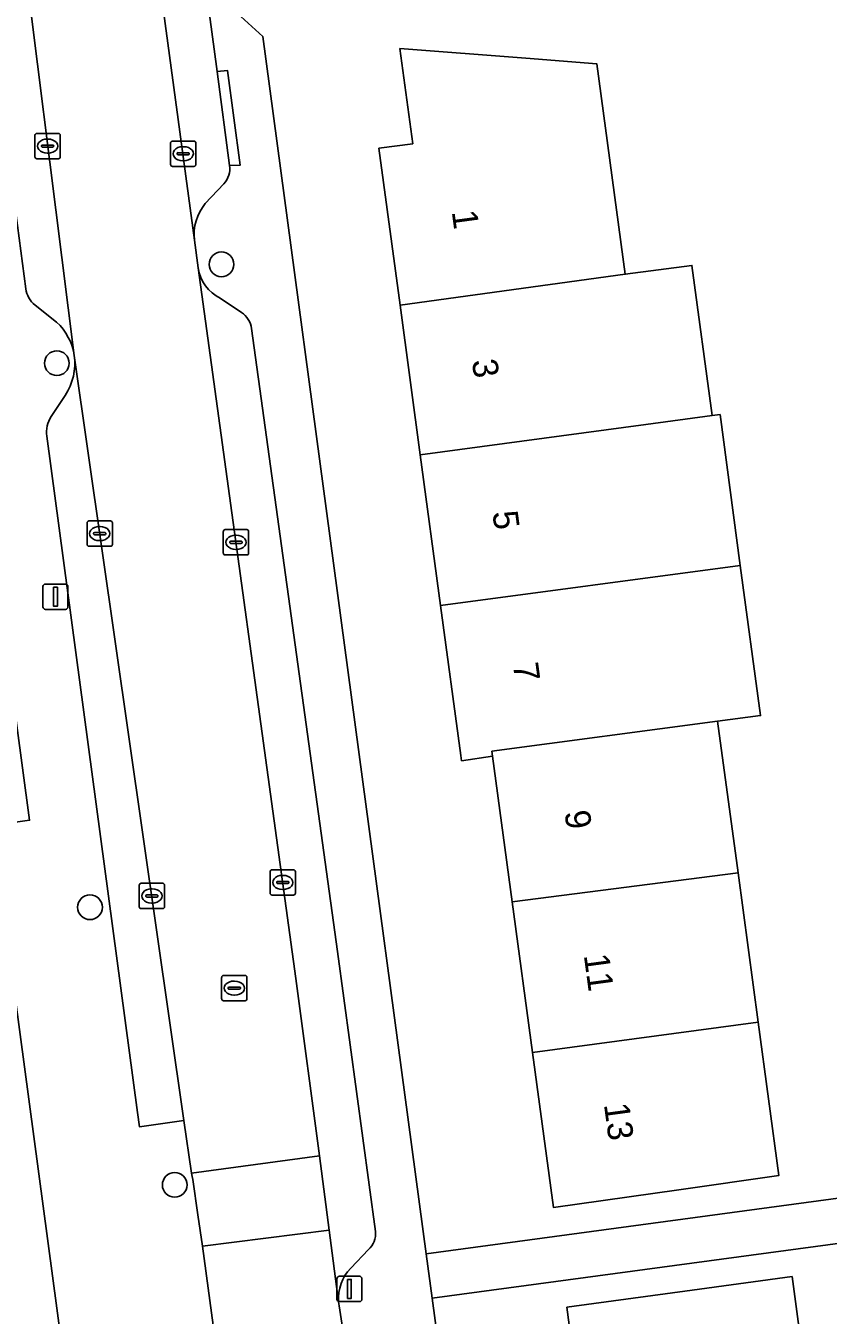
# Model space of a CAD drawing. Extents: x 163426 to 164192, y 380329 to 381641.
# Drawn here: x 163541.2 to 163572.9, y 381442.8 to 381493.9 of the extents above; entities that cross this region are included whole.
import ezdxf

# ---------------------------------------------------------------- set-up
doc = ezdxf.new("R2010")
doc.units = 0
for name, color, linetype in [('IMGEO_Boom', 7, 'Continuous'), ('IMGEO_Erf', 7, 'Continuous'), ('IMGEO_Kolk', 7, 'Continuous'), ('IMGEO_Lichtmast', 7, 'Continuous'), ('IMGEO_Pand', 7, 'Continuous'), ('IMGEO_Pand_nummerreeks', 7, 'Continuous'), ('IMGEO_Parkeervlak_open', 7, 'Continuous'), ('IMGEO_Rijbaan_lokaal_open', 7, 'Continuous'), ('IMGEO_Rioolput', 7, 'Continuous'), ('IMGEO_Voetpad_open', 7, 'Continuous')]:
    doc.layers.add(name, color=color, linetype=linetype)

msp = doc.modelspace()

# ---------------------------------------------------------------- linework, layer by layer
at = {"layer": 'IMGEO_Boom'}
for centre in [(163548.902, 381484.415), (163542.391, 381480.505), (163543.702, 381458.979), (163547.053, 381447.995)]:
    msp.add_circle(centre, 0.489, dxfattribs=at)
at = {"layer": 'IMGEO_Erf'}
for points in [[(163539.823, 381462.212), (163541.312, 381462.422), (163536.277, 381500), (163535.961, 381502.355), (163535.005, 381502.264), (163513.264, 381499.338), (163523.981, 381419.703), (163545.149, 381422.545)], [(163570.944, 381448.362), (163566.984, 381447.803), (163562.033, 381447.104), (163561.206, 381453.238), (163560.404, 381459.187), (163559.625, 381464.96), (163558.397, 381464.774), (163558.368, 381464.987), (163557.569, 381470.913), (163556.764, 381476.879), (163555.964, 381482.806), (163555.127, 381489.007), (163556.465, 381489.187), (163555.958, 381492.955), (163560.943, 381492.567), (163563.751, 381492.348), (163564.872, 381484.021), (163567.508, 381484.373), (163568.308, 381478.43), (163568.618, 381478.472), (163569.422, 381472.502), (163570.222, 381466.564), (163568.524, 381466.338), (163569.331, 381460.342), (163570.128, 381454.426)]]:
    msp.add_lwpolyline(points, close=True, dxfattribs=at)
for points in [[(163549.67, 381494.227), (163550.532, 381493.434), (163556.995, 381445.271), (163583.148, 381448.798)], [(163581.439, 381442.03), (163580.811, 381446.687), (163557.232, 381443.507), (163566.206, 381376.628)], [(163563.384, 381436.962), (163562.564, 381443.153), (163567.519, 381443.827), (163571.471, 381444.365), (163572.3, 381438.127)]]:
    msp.add_lwpolyline(points, dxfattribs=at)
at = {"layer": 'IMGEO_Kolk'}
for p, q in [((163541.525, 381488.668), (163541.525, 381489.52)), ((163541.6, 381489.594), (163542.452, 381489.594)), ((163542.013, 381489.374), (163542.038, 381489.374)), ((163542.526, 381489.52), (163542.526, 381488.668)), ((163546.962, 381489.291), (163547.814, 381489.291)), ((163541.784, 381489.088), (163541.784, 381489.1)), ((163542.222, 381489.051), (163541.824, 381489.051)), ((163541.827, 381489.137), (163542.225, 381489.137)), ((163542.036, 381488.814), (163542.011, 381488.814)), ((163542.268, 381489.1), (163542.268, 381489.088)), ((163546.887, 381488.365), (163546.887, 381489.217)), ((163547.146, 381488.785), (163547.146, 381488.797)), ((163547.584, 381488.748), (163547.186, 381488.748)), ((163547.189, 381488.834), (163547.587, 381488.834)), ((163547.375, 381489.071), (163547.4, 381489.071)), ((163547.63, 381488.797), (163547.63, 381488.785)), ((163547.888, 381489.217), (163547.888, 381488.365)), ((163542.452, 381488.594), (163541.6, 381488.594)), ((163547.814, 381488.291), (163546.962, 381488.291)), ((163547.398, 381488.511), (163547.373, 381488.511)), ((163543.587, 381473.337), (163543.587, 381474.189)), ((163543.662, 381474.263), (163544.514, 381474.263)), ((163544.075, 381474.043), (163544.1, 381474.043)), ((163544.588, 381474.189), (163544.588, 381473.337)), ((163543.846, 381473.757), (163543.846, 381473.769)), ((163544.284, 381473.72), (163543.886, 381473.72)), ((163543.889, 381473.806), (163544.287, 381473.806)), ((163544.098, 381473.483), (163544.073, 381473.483)), ((163544.33, 381473.769), (163544.33, 381473.757)), ((163548.975, 381472.992), (163548.975, 381473.844)), ((163549.05, 381473.918), (163549.902, 381473.918)), ((163549.277, 381473.461), (163549.675, 381473.461)), ((163549.463, 381473.698), (163549.488, 381473.698)), ((163549.976, 381473.844), (163549.976, 381472.992)), ((163544.514, 381473.263), (163543.662, 381473.263)), ((163549.234, 381473.412), (163549.234, 381473.424)), ((163549.672, 381473.375), (163549.274, 381473.375)), ((163549.486, 381473.138), (163549.461, 381473.138)), ((163549.718, 381473.424), (163549.718, 381473.412)), ((163549.902, 381472.918), (163549.05, 381472.918)), ((163550.827, 381459.533), (163550.827, 381460.385)), ((163550.902, 381460.459), (163551.754, 381460.459)), ((163551.315, 381460.239), (163551.34, 381460.239)), ((163551.828, 381460.385), (163551.828, 381459.533)), ((163545.648, 381459), (163545.648, 381459.852)), ((163545.723, 381459.926), (163546.575, 381459.926)), ((163546.136, 381459.706), (163546.161, 381459.706)), ((163546.649, 381459.852), (163546.649, 381459)), ((163551.086, 381459.953), (163551.086, 381459.965)), ((163551.524, 381459.916), (163551.126, 381459.916)), ((163551.129, 381460.002), (163551.527, 381460.002)), ((163551.338, 381459.679), (163551.313, 381459.679)), ((163551.57, 381459.965), (163551.57, 381459.953)), ((163545.907, 381459.42), (163545.907, 381459.432)), ((163546.345, 381459.383), (163545.947, 381459.383)), ((163545.95, 381459.469), (163546.348, 381459.469)), ((163546.391, 381459.432), (163546.391, 381459.42)), ((163551.754, 381459.459), (163550.902, 381459.459)), ((163546.575, 381458.926), (163545.723, 381458.926)), ((163546.159, 381459.146), (163546.134, 381459.146))]:
    msp.add_line(p, q, dxfattribs=at)
for points in [[(163541.525, 381488.668), (163541.525, 381489.52)], [(163541.6, 381489.594), (163542.452, 381489.594)], [(163542.526, 381489.52), (163542.526, 381488.668)], [(163546.962, 381489.291), (163547.814, 381489.291)], [(163546.887, 381488.365), (163546.887, 381489.217)], [(163547.888, 381489.217), (163547.888, 381488.365)], [(163542.452, 381488.594), (163541.6, 381488.594)], [(163547.814, 381488.291), (163546.962, 381488.291)], [(163543.587, 381473.337), (163543.587, 381474.189)], [(163543.662, 381474.263), (163544.514, 381474.263)], [(163544.588, 381474.189), (163544.588, 381473.337)], [(163548.975, 381472.992), (163548.975, 381473.844)], [(163549.05, 381473.918), (163549.902, 381473.918)], [(163549.976, 381473.844), (163549.976, 381472.992)], [(163544.514, 381473.263), (163543.662, 381473.263)], [(163549.902, 381472.918), (163549.05, 381472.918)], [(163550.827, 381459.533), (163550.827, 381460.385)], [(163550.902, 381460.459), (163551.754, 381460.459)], [(163551.828, 381460.385), (163551.828, 381459.533)], [(163545.648, 381459), (163545.648, 381459.852)], [(163545.723, 381459.926), (163546.575, 381459.926)], [(163546.649, 381459.852), (163546.649, 381459)], [(163551.754, 381459.459), (163550.902, 381459.459)], [(163546.575, 381458.926), (163545.723, 381458.926)]]:
    msp.add_lwpolyline(points, dxfattribs=at)
for centre, radius, start, end in [((163541.602, 381489.518), 0.0765, 91.552, 178.448), ((163541.602, 381489.518), 0.0765, 91.552, 178.448), ((163542.45, 381489.518), 0.0765, 1.552, 88.448), ((163542.45, 381489.518), 0.0765, 1.552, 88.448), ((163546.964, 381489.215), 0.0765, 91.552, 178.448), ((163546.964, 381489.215), 0.0765, 91.552, 178.448), ((163547.812, 381489.215), 0.0765, 1.552, 88.448), ((163547.812, 381489.215), 0.0765, 1.552, 88.448), ((163541.824, 381489.097), 0.0403, 85.8775, 175.7526), ((163541.821, 381489.087), 0.0366, 178.938, 274.7102), ((163542.225, 381489.094), 0.043, 264.8664, 352.4533), ((163542.229, 381489.099), 0.0386, 1.7309, 96.639), ((163547.186, 381488.794), 0.0403, 85.8775, 175.7526), ((163547.183, 381488.784), 0.0366, 178.938, 274.7102), ((163547.587, 381488.791), 0.043, 264.8664, 352.4533), ((163547.591, 381488.796), 0.0386, 1.7309, 96.639), ((163541.602, 381488.67), 0.0765, 181.552, 268.448), ((163541.602, 381488.67), 0.0765, 181.552, 268.448), ((163542.45, 381488.67), 0.0765, 271.552, 358.448), ((163542.45, 381488.67), 0.0765, 271.552, 358.448), ((163546.964, 381488.367), 0.0765, 181.552, 268.448), ((163546.964, 381488.367), 0.0765, 181.552, 268.448), ((163547.812, 381488.367), 0.0765, 271.552, 358.448), ((163547.812, 381488.367), 0.0765, 271.552, 358.448), ((163543.664, 381474.187), 0.0765, 91.552, 178.448), ((163543.664, 381474.187), 0.0765, 91.552, 178.448), ((163544.512, 381474.187), 0.0765, 1.552, 88.448), ((163544.512, 381474.187), 0.0765, 1.552, 88.448), ((163543.886, 381473.766), 0.0403, 85.8775, 175.7526), ((163543.883, 381473.756), 0.0366, 178.938, 274.7102), ((163544.287, 381473.763), 0.043, 264.8664, 352.4533), ((163544.291, 381473.768), 0.0386, 1.7309, 96.639), ((163549.052, 381473.842), 0.0765, 91.552, 178.448), ((163549.052, 381473.842), 0.0765, 91.552, 178.448), ((163549.274, 381473.421), 0.0403, 85.8775, 175.7526), ((163549.679, 381473.423), 0.0386, 1.7309, 96.639), ((163549.9, 381473.842), 0.0765, 1.552, 88.448), ((163549.9, 381473.842), 0.0765, 1.552, 88.448), ((163543.664, 381473.339), 0.0765, 181.552, 268.448), ((163543.664, 381473.339), 0.0765, 181.552, 268.448), ((163544.512, 381473.339), 0.0765, 271.552, 358.448), ((163544.512, 381473.339), 0.0765, 271.552, 358.448), ((163549.052, 381472.994), 0.0765, 181.552, 268.448), ((163549.052, 381472.994), 0.0765, 181.552, 268.448), ((163549.271, 381473.411), 0.0366, 178.938, 274.7102), ((163549.675, 381473.418), 0.043, 264.8664, 352.4533), ((163549.9, 381472.994), 0.0765, 271.552, 358.448), ((163549.9, 381472.994), 0.0765, 271.552, 358.448), ((163550.904, 381460.383), 0.0765, 91.552, 178.448), ((163550.904, 381460.383), 0.0765, 91.552, 178.448), ((163551.752, 381460.383), 0.0765, 1.552, 88.448), ((163551.752, 381460.383), 0.0765, 1.552, 88.448), ((163545.725, 381459.85), 0.0765, 91.552, 178.448), ((163545.725, 381459.85), 0.0765, 91.552, 178.448), ((163546.573, 381459.85), 0.0765, 1.552, 88.448), ((163546.573, 381459.85), 0.0765, 1.552, 88.448), ((163551.126, 381459.962), 0.0403, 85.8775, 175.7526), ((163551.123, 381459.952), 0.0366, 178.938, 274.7102), ((163551.527, 381459.959), 0.043, 264.8664, 352.4533), ((163551.531, 381459.964), 0.0386, 1.7309, 96.639), ((163545.947, 381459.429), 0.0403, 85.8775, 175.7526), ((163545.944, 381459.419), 0.0366, 178.938, 274.7102), ((163546.348, 381459.426), 0.043, 264.8664, 352.4533), ((163546.352, 381459.431), 0.0386, 1.7309, 96.639), ((163550.904, 381459.535), 0.0765, 181.552, 268.448), ((163550.904, 381459.535), 0.0765, 181.552, 268.448), ((163551.752, 381459.535), 0.0765, 271.552, 358.448), ((163551.752, 381459.535), 0.0765, 271.552, 358.448), ((163545.725, 381459.002), 0.0765, 181.552, 268.448), ((163545.725, 381459.002), 0.0765, 181.552, 268.448), ((163546.573, 381459.002), 0.0765, 271.552, 358.448), ((163546.573, 381459.002), 0.0765, 271.552, 358.448)]:
    msp.add_arc(centre, radius, start, end, dxfattribs=at)
for centre, major_axis, ratio, start_param, end_param in [((163542.012, 381489.094), (-0.387, 0.002), 0.722429, 4.712389, 7.853982), ((163542.037, 381489.094), (-0.39, 0.002), 0.717154, 1.570796, 4.712389), ((163547.374, 381488.791), (-0.387, 0.002), 0.722429, 4.712389, 7.853982), ((163547.399, 381488.791), (-0.39, 0.002), 0.717154, 1.570796, 4.712389), ((163544.074, 381473.763), (-0.387, 0.002), 0.722429, 4.712389, 7.853982), ((163544.099, 381473.763), (-0.39, 0.002), 0.717154, 1.570796, 4.712389), ((163549.462, 381473.418), (-0.387, 0.002), 0.722429, 4.712389, 7.853982), ((163549.487, 381473.418), (-0.39, 0.002), 0.717154, 1.570796, 4.712389), ((163551.314, 381459.959), (-0.387, 0.002), 0.722429, 4.712389, 7.853982), ((163551.339, 381459.959), (-0.39, 0.002), 0.717154, 1.570796, 4.712389), ((163546.135, 381459.426), (-0.387, 0.002), 0.722429, 4.712389, 7.853982), ((163546.16, 381459.426), (-0.39, 0.002), 0.717154, 1.570796, 4.712389)]:
    msp.add_ellipse(centre, major_axis=major_axis, ratio=ratio, start_param=start_param, end_param=end_param, dxfattribs=at)
at = {"layer": 'IMGEO_Lichtmast'}
for p, q in [((163541.842, 381470.864), (163541.842, 381471.664)), ((163541.842, 381471.664), (163541.842, 381470.864)), ((163541.942, 381471.764), (163542.732, 381471.764)), ((163542.732, 381471.764), (163541.942, 381471.764)), ((163542.832, 381471.664), (163542.832, 381470.864)), ((163542.832, 381470.864), (163542.832, 381471.664)), ((163542.732, 381470.764), (163541.942, 381470.764)), ((163541.942, 381470.764), (163542.732, 381470.764)), ((163553.567, 381444.377), (163554.357, 381444.377)), ((163554.357, 381444.377), (163553.567, 381444.377)), ((163553.467, 381443.477), (163553.467, 381444.277)), ((163553.467, 381444.277), (163553.467, 381443.477)), ((163554.457, 381444.277), (163554.457, 381443.477)), ((163554.457, 381443.477), (163554.457, 381444.277)), ((163554.357, 381443.377), (163553.567, 381443.377)), ((163553.567, 381443.377), (163554.357, 381443.377))]:
    msp.add_line(p, q, dxfattribs=at)
for points in [[(163542.262, 381471.639), (163542.412, 381471.639), (163542.412, 381470.889), (163542.262, 381470.889), (163542.262, 381471.639)], [(163553.887, 381444.252), (163554.037, 381444.252), (163554.037, 381443.502), (163553.887, 381443.502), (163553.887, 381444.252)]]:
    msp.add_lwpolyline(points, dxfattribs=at)
for centre, start, end in [((163541.942, 381471.664), 90, 180), ((163541.942, 381471.664), 90, 180), ((163542.732, 381471.664), 0, 90), ((163542.732, 381471.664), 360, 90), ((163541.942, 381470.864), 180, 270), ((163541.942, 381470.864), 180, 270), ((163542.732, 381470.864), 270, 0), ((163542.732, 381470.864), 270, 0), ((163553.567, 381444.277), 90, 180), ((163553.567, 381444.277), 90, 180), ((163554.357, 381444.277), 0, 90), ((163554.357, 381444.277), 360, 90), ((163553.567, 381443.477), 180, 270), ((163553.567, 381443.477), 180, 270), ((163554.357, 381443.477), 270, 0), ((163554.357, 381443.477), 270, 0)]:
    msp.add_arc(centre, 0.1, start, end, dxfattribs=at)
at = {"layer": 'IMGEO_Pand'}
for points in [[(163555.964, 381482.806), (163564.872, 381484.021), (163563.751, 381492.348), (163560.943, 381492.567), (163555.958, 381492.955), (163556.465, 381489.187), (163555.127, 381489.007)], [(163556.764, 381476.879), (163565.691, 381478.079), (163568.308, 381478.43), (163567.508, 381484.373), (163564.872, 381484.021), (163555.964, 381482.806)], [(163569.422, 381472.502), (163568.618, 381478.472), (163568.308, 381478.43), (163565.691, 381478.079), (163556.764, 381476.879), (163557.569, 381470.913)], [(163569.422, 381472.502), (163557.569, 381470.913), (163558.368, 381464.987), (163558.397, 381464.774), (163559.625, 381464.96), (163559.599, 381465.151), (163568.524, 381466.338), (163570.222, 381466.564)], [(163568.524, 381466.338), (163559.599, 381465.151), (163559.625, 381464.96), (163560.404, 381459.187), (163569.331, 381460.342)], [(163570.128, 381454.426), (163569.331, 381460.342), (163560.404, 381459.187), (163561.206, 381453.238)], [(163570.128, 381454.426), (163561.206, 381453.238), (163562.033, 381447.104), (163566.984, 381447.803), (163570.944, 381448.362)], [(163563.384, 381436.962), (163572.3, 381438.127), (163571.471, 381444.365), (163567.519, 381443.827), (163562.564, 381443.153)]]:
    msp.add_lwpolyline(points, close=True, dxfattribs=at)
at = {"layer": 'IMGEO_Parkeervlak_open'}
for points in [[(163542.971, 381521.306), (163545.852, 381500), (163547.83, 381485.368)], [(163549.225, 381488.332), (163548.727, 381492.039), (163547.658, 381500), (163545.129, 381518.832)], [(163537.364, 381512.278), (163538.982, 381500), (163541.163, 381483.452)], [(163543.08, 381480.808), (163540.658, 381500)], [(163548.263, 381486.824), (163548.992, 381487.606)], [(163547.979, 381484.273), (163551.848, 381456.16), (163552.773, 381449.148), (163553.162, 381446.201), (163553.536, 381443.371)], [(163541.53, 381482.804), (163542.383, 381482.127)], [(163549.695, 381482.511), (163548.854, 381483.073)], [(163554.995, 381446.148), (163553.497, 381457.225), (163550.094, 381481.871)], [(163541.994, 381477.616), (163545.579, 381450.857), (163545.661, 381450.286), (163547.416, 381450.538), (163543.08, 381480.808)], [(163542.723, 381479.23), (163542.17, 381478.391)], [(163554.012, 381444.698), (163554.715, 381445.435)]]:
    msp.add_lwpolyline(points, dxfattribs=at)
for centre, radius, start, end in [((163548.321, 381488.222), 0.911, 317.4577, 6.9557), ((163549.769, 381485.584), 1.951, 140.5252, 186.3509), ((163549.592, 381484.53), 1.633, 189.0479, 243.1487), ((163542.151, 381483.584), 0.997, 187.6006, 231.4502), ((163540.855, 381480.476), 2.25, 8.4886, 47.218), ((163549.183, 381481.747), 0.92, 7.7306, 56.1513), ((163540.788, 381480.497), 2.313, 326.784, 7.7205), ((163543.121, 381477.768), 1.137, 146.7503, 187.6603), ((163554.122, 381446.079), 0.876, 312.6217, 4.4977), ((163555.231, 381443.512), 1.701, 135.7848, 184.749)]:
    msp.add_arc(centre, radius, start, end, dxfattribs=at)
at = {"layer": 'IMGEO_Rijbaan_lokaal_open'}
for points in [[(163547.714, 381448.459), (163552.773, 381449.148), (163551.848, 381456.16), (163547.979, 381484.273), (163547.83, 381485.368), (163545.852, 381500), (163542.971, 381521.306), (163542.879, 381522.123), (163542.729, 381523.405), (163542.764, 381523.704), (163537.726, 381523.034), (163537.691, 381522.857), (163537.994, 381521.009), (163538.748, 381515.131), (163540.658, 381500), (163543.08, 381480.808), (163547.416, 381450.538)], [(163552.773, 381449.148), (163547.714, 381448.459), (163547.744, 381448.327), (163547.772, 381448.204), (163547.973, 381446.804), (163548.151, 381445.563), (163553.162, 381446.201)], [(163553.981, 381440.08), (163553.761, 381441.842), (163553.557, 381443.21), (163553.536, 381443.371), (163553.162, 381446.201), (163548.151, 381445.563), (163548.736, 381441.267), (163548.986, 381439.398), (163554.854, 381395.594), (163559.875, 381396.219)]]:
    msp.add_lwpolyline(points, close=True, dxfattribs=at)
at = {"layer": 'IMGEO_Rioolput'}
for p, q in [((163548.909, 381455.352), (163548.909, 381456.204)), ((163548.984, 381456.278), (163549.836, 381456.278)), ((163549.91, 381456.204), (163549.91, 381455.352)), ((163549.168, 381455.772), (163549.168, 381455.784)), ((163549.606, 381455.735), (163549.208, 381455.735)), ((163549.211, 381455.821), (163549.609, 381455.821)), ((163549.397, 381456.058), (163549.422, 381456.058)), ((163549.652, 381455.784), (163549.652, 381455.772)), ((163549.836, 381455.278), (163548.984, 381455.278)), ((163549.42, 381455.498), (163549.395, 381455.498))]:
    msp.add_line(p, q, dxfattribs=at)
for points in [[(163548.909, 381455.352), (163548.909, 381456.204)], [(163548.984, 381456.278), (163549.836, 381456.278)], [(163549.91, 381456.204), (163549.91, 381455.352)], [(163549.836, 381455.278), (163548.984, 381455.278)]]:
    msp.add_lwpolyline(points, dxfattribs=at)
for centre, radius, start, end in [((163548.986, 381456.202), 0.0765, 91.552, 178.448), ((163548.986, 381456.202), 0.0765, 91.552, 178.448), ((163549.834, 381456.202), 0.0765, 1.552, 88.448), ((163549.834, 381456.202), 0.0765, 1.552, 88.448), ((163549.208, 381455.781), 0.0403, 85.8775, 175.7526), ((163549.205, 381455.771), 0.0366, 178.938, 274.7102), ((163549.609, 381455.778), 0.043, 264.8664, 352.4533), ((163549.613, 381455.783), 0.0386, 1.7309, 96.639), ((163548.986, 381455.354), 0.0765, 181.552, 268.448), ((163548.986, 381455.354), 0.0765, 181.552, 268.448), ((163549.834, 381455.354), 0.0765, 271.552, 358.448), ((163549.834, 381455.354), 0.0765, 271.552, 358.448)]:
    msp.add_arc(centre, radius, start, end, dxfattribs=at)
for centre, major_axis, ratio, start_param, end_param in [((163549.396, 381455.778), (-0.387, 0.002), 0.722429, 4.712389, 7.853982), ((163549.421, 381455.778), (-0.39, 0.002), 0.717154, 1.570796, 4.712389)]:
    msp.add_ellipse(centre, major_axis=major_axis, ratio=ratio, start_param=start_param, end_param=end_param, dxfattribs=at)
at = {"layer": 'IMGEO_Voetpad_open'}
for points in [[(163538.748, 381515.131), (163537.994, 381521.009), (163537.691, 381522.857), (163537.726, 381523.034), (163537.586, 381523.962), (163537.28, 381526.001), (163532.089, 381524.073), (163534.881, 381503.195), (163535.005, 381502.264), (163535.961, 381502.355), (163536.277, 381500), (163541.312, 381462.422), (163539.823, 381462.212), (163545.149, 381422.545), (163545.331, 381421.187), (163551.459, 381375.552), (163552.956, 381375.749), (163557.372, 381342.692), (163557.774, 381339.564)], [(163571.177, 381345.417), (163569.239, 381353.811), (163569.01, 381355.444), (163568.044, 381362.93), (163566.405, 381375.146), (163566.206, 381376.628), (163557.232, 381443.507), (163556.995, 381445.271), (163550.532, 381493.434), (163549.67, 381494.227), (163548.887, 381500), (163545.916, 381521.903)], [(163545.129, 381518.832), (163547.658, 381500), (163548.727, 381492.039), (163549.144, 381492.08), (163549.638, 381488.335), (163549.225, 381488.332)], [(163541.163, 381483.452), (163538.982, 381500), (163537.364, 381512.278)], [(163548.992, 381487.606), (163548.263, 381486.824)], [(163547.83, 381485.368), (163547.979, 381484.273)], [(163542.383, 381482.127), (163541.53, 381482.804)], [(163548.854, 381483.073), (163549.695, 381482.511)], [(163550.094, 381481.871), (163553.497, 381457.225), (163554.995, 381446.148)], [(163542.17, 381478.391), (163542.723, 381479.23)], [(163548.986, 381439.398), (163548.736, 381441.267), (163548.151, 381445.563), (163547.973, 381446.804), (163547.772, 381448.204), (163547.744, 381448.327), (163547.714, 381448.459), (163547.416, 381450.538), (163545.661, 381450.286), (163545.579, 381450.857), (163541.994, 381477.616)], [(163583.148, 381448.798), (163556.995, 381445.271), (163557.232, 381443.507), (163580.811, 381446.687)], [(163554.715, 381445.435), (163554.012, 381444.698)], [(163553.536, 381443.371), (163553.557, 381443.21), (163553.761, 381441.842), (163553.981, 381440.08)]]:
    msp.add_lwpolyline(points, dxfattribs=at)
msp.add_lwpolyline([(163548.727, 381492.039), (163549.225, 381488.332), (163549.638, 381488.335), (163549.144, 381492.08)], close=True, dxfattribs=at)
for centre, radius, start, end in [((163548.321, 381488.222), 0.911, 317.4577, 6.9557), ((163549.769, 381485.584), 1.951, 140.5252, 186.3509), ((163549.592, 381484.53), 1.633, 189.0479, 243.1487), ((163542.151, 381483.584), 0.997, 187.6006, 231.4502), ((163540.855, 381480.476), 2.25, 8.4886, 47.218), ((163549.183, 381481.747), 0.92, 7.7306, 56.1513), ((163540.788, 381480.497), 2.313, 326.784, 7.7205), ((163543.121, 381477.768), 1.137, 146.7503, 187.6603), ((163554.122, 381446.079), 0.876, 312.6217, 4.4977), ((163555.231, 381443.512), 1.701, 135.7848, 184.749)]:
    msp.add_arc(centre, radius, start, end, dxfattribs=at)

# ---------------------------------------------------------------- texts
at = {"layer": 'IMGEO_Pand_nummerreeks'}
for s, rotation, p in [('1', 277.6851, (163558.008, 381486.501)), ('3', 277.6851, (163558.803, 381480.609)), ('5', 277.6851, (163559.614, 381474.605)), ('7', 277.6832, (163560.424, 381468.6)), ('9', 277.6832, (163562.466, 381462.753)), ('11', 277.6804, (163563.23, 381457.08)), ('13', 277.6804, (163564.026, 381451.177))]:
    msp.add_text(s, height=1, rotation=rotation, dxfattribs=at).set_placement(p)

doc.saveas('drawing.dxf')
